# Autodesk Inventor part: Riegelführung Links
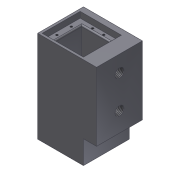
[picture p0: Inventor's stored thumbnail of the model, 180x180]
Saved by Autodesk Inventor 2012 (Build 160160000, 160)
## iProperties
Created: 2012-01
Part Number: Riegelführung Links
Material: S 235JR+AR
Document SubType Name: Modeling
Designer: Dangendorf
Density: 7.85 g/cm^3
Mass: 3265.61 g
Surface Area: 570.959 cm^2
Volume: 416.002 cm^3
Author: Dangendorf
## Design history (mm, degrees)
sketch "Skizze1"
  geometry: L1 (-45, 35)-(45, 35); L2 (45, 35)-(45, -35); L3 (45, -35)-(-45, -35); L4 (-45, -35)-(-45, 35); 3 further points
  constraints: 8 end point, 2 midpoint, 2 parallel, 1 horizontal, 1 horizontal alignment, 1 perpendicular, 1 vertical alignment
  dimensions: "d0" = 90 distance of L1.start L1.end; "d1" = 70 distance of L3.end L1.start
extrude "Extrusion1" new body sketch "Skizze1" distance "d2" = 140; taper "d3" = 0 deg
chamfer "Fase1" distance "d33" = 2; stored, may be unused: second distance "d34" = 2, angle "d35" = 45 deg
sketch "Skizze5"
  geometry: L1 (45, -35)-(45, 35) reference; L2 (-11, -23.5)-(31, -23.5); L3 (31, -23.5)-(31, 18.5); L4 (31, 18.5)-(-11, 18.5); L5 (-11, 18.5)-(-11, -23.5); L6 (-43, -35)-(45, -35) reference; 1 further point
  constraints: 8 end point, 2 parallel, 1 horizontal, 1 perpendicular
  dimensions: "d36" = 42 distance of L4.end L2.start; "d37" = 42 distance of L2.start L2.end; "d38" = 14 distance between parallel lines of L1 L3; "d57" = 11.5 distance between parallel lines of L6 L2
extrude "Extrusion4" cut sketch "Skizze5" stored distance "d40" = 104.5; taper "d41" = 0 deg
sketch "Skizze11"
  geometry: L1 (88, -140)-(0, -140) reference; L2 (90, -141.871)-(70, -141.871); L3 (70, -141.871)-(70, -104.5); L4 (70, -104.5)-(90, -104.5); L5 (90, -104.5)-(90, -141.871); 1 further point
  constraints: 8 end point, 2 parallel, 1 horizontal, 1 perpendicular
  dimensions: "d96" = 20 distance between parallel lines of L3 L5; "d97" = 35.5 distance between parallel lines of L4 L1
extrude "Extrusion6" cut sketch "Skizze11" stored distance "d98" = 10; taper "d99" = 0 deg
sketch "Skizze15"
  geometry: L1 (-31, -23.5)-(-31, 18.5) reference; L2 (-31, 18.5)-(11, 18.5) reference; L3 (11, 18.5)-(11, -23.5) reference; L4 (11, -23.5)-(-31, -23.5) reference; L5 (-41.5, 26.5)-(21.5, 26.5); L6 (21.5, 26.5)-(21.5, -31.5); L7 (21.5, -31.5)-(-41.5, -31.5); L8 (-41.5, -31.5)-(-41.5, 26.5); L9 (-45, -35)-(-45, 35) reference; L10 (45, -35)-(-45, -35) reference; 1 further point
  constraints: 8 end point, 2 parallel, 1 horizontal, 1 perpendicular
  dimensions: "d124" = 63 distance of L5.start L5.end; "d125" = 58 distance of L7.end L5.start; "d133" = 3.5 distance between parallel lines of L7 L10; "d134" = 3.5 distance between parallel lines of L8 L9
extrude "Extrusion7" cut sketch "Skizze15" distance "d128" = 9; taper "d129" = 0 deg
fillet "Rundung3" dims "d135" = 2
sketch "Skizze19"
  geometry: L1 (-41.5, 26.5)-(-41.5, -31.5); L2 (-41.5, -31.5)-(21.5, -31.5); L3 (21.5, 26.5)-(-41.5, 26.5); L4 (17, 22.5)-(-37, 22.5); L5 (-37, 22.5)-(-37, -27.5); L6 (-37, -27.5)-(17, -27.5); L7 (17, -27.5)-(17, 22.5); L8 (-18.5, 22.5)-(-18.5, -27.5); L9 (-1.5, 22.5)-(-1.5, -27.5); L10 (-37, 8.5)-(17, 8.5); L11 (17, -13.5)-(-37, -13.5); 10 further points
  constraints: 22 end point, 2 parallel, 1 horizontal, 1 perpendicular
  dimensions: "d175" = 54 distance of L5.end L6.end; "d176" = 50 distance of L4.end L5.end; "d177" = 4 distance between parallel lines of L3 L4; "d178" = 18.5 distance between parallel lines of L8 L5; "d179" = 18.5 distance between parallel lines of L7 L9; "d180" = 4.5 distance between parallel lines of L1 L5; "d181" = 18 distance between parallel lines of L2 L11; "d182" = 18 distance between parallel lines of L3 L10
hole "Bohrung12" sketch "Skizze19" at (-37, 8.5), (-37, -13.5), (-18.5, -27.5), (-1.5, -27.5), (-18.5, 22.5), (-1.5, 22.5), (17, 8.5), (17, -13.5) diameter "d183" = 3.242; stored, may be unused: countersink angle "d187" = 90 deg, drill point angle "d189" = 118 deg; dims "d184" = 6, "d185" = 4, "d186" = 2, "d188" = 8
sketch "Skizze20"
  geometry: L1 (104.5, 70)-(0, 70) reference; L2 (0, 70)-(0, 0) reference; 3 further points
  dimensions: "d200" = 35 distance from line of L1 point (25, 35); "d201" = 35 distance from line of L1 point (75, 35); "d202" = 25 distance from line of point (25, 35) L2; "d203" = 75 distance from line of L2 point (75, 35)
hole "Bohrung14" sketch "Skizze20" at (25, 35), (75, 35) diameter "d204" = 13.835; stored, may be unused: countersink angle "d208" = 90 deg, drill point angle "d210" = 118 deg; dims "d205" = 26, "d206" = 4, "d207" = 2, "d209" = 28
sketch "Skizze22"
  geometry: L1 (-25, -35)-(45, -35) reference; L2 (45, -35)-(45, 35) reference; L3 (45, 35)-(-25, 35) reference; 5 further points
  dimensions: "d220" = 59 distance from line of L2 point (-14, -26.5); "d221" = 59 distance from line of L2 point (-14, 21.5); "d222" = 13.5 distance from line of L3 point (-14, 21.5); "d223" = 8.5 distance from line of L1 point (-14, -26.5); "d224" = 11 distance from line of L2 point (34, -26.5); "d225" = 8.5 distance from line of L1 point (34, -26.5); "d226" = 13.5 distance from line of L3 point (34, 21.5); "d227" = 11 distance from line of L2 point (34, 21.5)
hole "Bohrung15" sketch "Skizze22" at (-14, -26.5), (-14, 21.5), (34, 21.5), (34, -26.5) diameter "d228" = 6.647; stored, may be unused: countersink angle "d232" = 90 deg, drill point angle "d234" = 118 deg; dims "d229" = 25, "d230" = 4, "d231" = 2, "d233" = 30
node "Volumenkörper1"
node "Skizze13"
node "Skizze14"
